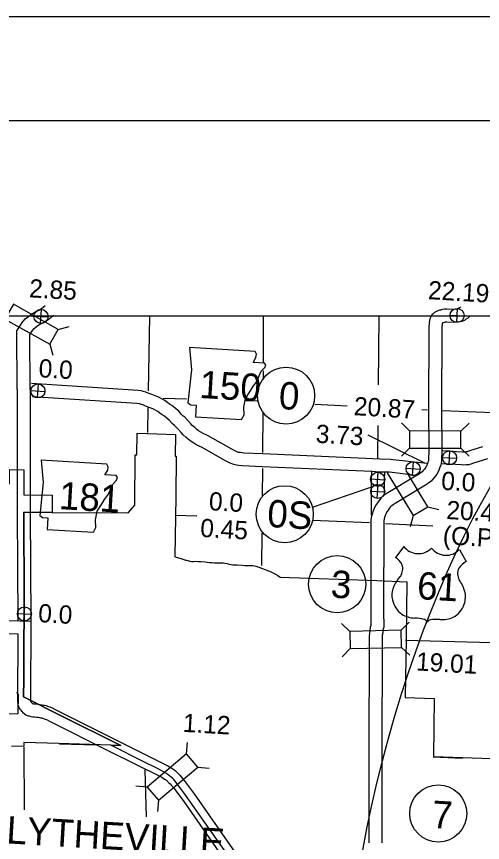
# Model space of a CAD drawing. Extents: x 1366406 to 1373462, y 376856 to 381998.
# Drawn here: x 1368068.6 to 1368242.9, y 380963.4 to 381272.9 of the extents above; entities that cross this region are included whole.
import ezdxf

# ---------------------------------------------------------------- set-up
doc = ezdxf.new("R2010")
doc.units = 0
for name, color, linetype in [('10', 7, 'Continuous'), ('15', 7, 'Continuous'), ('20', 7, 'Continuous'), ('21', 7, 'Continuous'), ('22', 7, 'Continuous'), ('25', 7, 'Continuous'), ('26', 7, 'Continuous'), ('27', 7, 'Continuous'), ('4', 7, 'Continuous'), ('5', 7, 'Continuous'), ('58', 7, 'Continuous'), ('6', 7, 'Continuous'), ('Default', 7, 'Continuous'), ('R_Border', 7, 'Continuous'), ('R_No Plot', 7, 'Continuous')]:
    doc.layers.add(name, color=color, linetype=linetype)

msp = doc.modelspace()

# ---------------------------------------------------------------- linework, layer by layer
at = {"layer": '10'}
for points in [[(1368068.72, 381155.1), (1368070.02, 381157.19), (1368070.68, 381158.2), (1368071.82, 381159.55), (1368073.08, 381160.5), (1368074.35, 381161.46), (1368075.71, 381162.23), (1368076.88, 381162.88), (1368077.85, 381163.48), (1368078.64, 381164.12), (1368079.34, 381164.66)], [(1368073.59, 381153.78), (1368074.1, 381154.54), (1368074.59, 381155.3), (1368075.17, 381155.98), (1368076.09, 381156.72), (1368076.97, 381157.38), (1368078.12, 381158.03), (1368079.39, 381158.71), (1368080.72, 381159.55), (1368081.7, 381160.34), (1368082.49, 381160.96)], [(1368068.79, 381133.08), (1368068.73, 381155.1)], [(1368073.65, 381133.1), (1368073.59, 381153.78)], [(1368073.65, 381133.1), (1368073.59, 381153.63)], [(1368204.48, 381107), (1368201.84, 381107.22), (1368160.75, 381109.02), (1368153.57, 381109.33), (1368152.33, 381109.53), (1368151.69, 381109.59), (1368151.3, 381109.68), (1368150.53, 381110), (1368149.08, 381110.73), (1368139.98, 381115.87), (1368138.36, 381116.6), (1368137.55, 381117.14), (1368136.7, 381117.69), (1368135.97, 381118.23), (1368135.23, 381118.87), (1368134.32, 381119.64), (1368133.8, 381120.26), (1368132.65, 381121.52), (1368131.53, 381122.72), (1368130.82, 381123.3), (1368130.34, 381123.73), (1368129.3, 381125), (1368127.94, 381126.15), (1368126.71, 381127.13), (1368125.86, 381127.65), (1368125.21, 381128.17), (1368124.08, 381129), (1368121.63, 381130.27), (1368118.59, 381131.48), (1368117.51, 381131.89), (1368116.89, 381132.13), (1368115.99, 381132.44), (1368115.29, 381132.58), (1368114.13, 381132.74), (1368074.18, 381135.33)], [(1368068.79, 381133.09), (1368068.84, 381087.06), (1368069.03, 381046.57)], [(1368073.65, 381133.09), (1368073.7, 381087.08), (1368073.9, 381046.43)], [(1368204.26, 381102.14), (1368201.53, 381102.37), (1368160.54, 381104.16), (1368153.07, 381104.49), (1368151.72, 381104.71), (1368150.94, 381104.78), (1368149.85, 381105.02), (1368148.51, 381105.57), (1368146.79, 381106.44), (1368137.77, 381111.53), (1368135.99, 381112.34), (1368134.89, 381113.08), (1368133.95, 381113.68), (1368132.94, 381114.42), (1368132.06, 381115.18), (1368130.87, 381116.19), (1368130.14, 381117.06), (1368129.08, 381118.23), (1368128.2, 381119.16), (1368127.65, 381119.61), (1368126.82, 381120.36), (1368125.82, 381121.58), (1368124.86, 381122.4), (1368123.93, 381123.13), (1368123.06, 381123.66), (1368122.25, 381124.32), (1368121.5, 381124.86), (1368119.6, 381125.85), (1368116.83, 381126.95), (1368115.79, 381127.34), (1368115.23, 381127.56), (1368114.72, 381127.74), (1368114.48, 381127.78), (1368113.64, 381127.9), (1368074.54, 381130.44)], [(1368242.98, 381111.68), (1368238.02, 381110.11), (1368237.17, 381109.83), (1368236.98, 381109.79), (1368236.85, 381109.77), (1368236.27, 381109.72), (1368235.89, 381109.66), (1368235.42, 381109.71), (1368233.21, 381109.83), (1368230.68, 381110.03), (1368228.08, 381110.14)], [(1368021.88, 381107.98), (1368036.86, 381077.38), (1368053.85, 381042.05), (1368069.03, 381041.63)], [(1368026.24, 381110.12), (1368041.23, 381079.5), (1368056.94, 381046.83), (1368073.92, 381046.36)], [(1368244.84, 381107.17), (1368239.52, 381105.49), (1368238.53, 381105.16), (1368237.78, 381104.97), (1368237.29, 381104.93), (1368236.84, 381104.89), (1368235.98, 381104.77), (1368235.06, 381104.86), (1368232.88, 381104.98), (1368230.39, 381105.18), (1368227.8, 381105.28)], [(1368222.06, 381105.39), (1368208.4, 381106.97), (1368204.48, 381107)], [(1368201.42, 381102.25), (1368201.41, 381102.16), (1368201.38, 381101.61), (1368201.23, 381100.63), (1368201.33, 381086.11)], [(1368217.93, 381100.97), (1368208.1, 381102.12), (1368204.26, 381102.14)], [(1368206.27, 381102), (1368206.22, 381101.12), (1368206.1, 381100.29), (1368206.14, 381093.75)], [(1368073.92, 381046.36), (1368073.75, 381017.15), (1368073.78, 381016.51), (1368073.81, 381016.29), (1368073.86, 381016.18), (1368073.94, 381016.09), (1368074.14, 381015.89), (1368074.42, 381015.6), (1368074.45, 381015.56), (1368074.53, 381015.54), (1368074.68, 381015.48), (1368074.86, 381015.44), (1368075.18, 381015.39), (1368075.8, 381015.34), (1368076.58, 381015.24), (1368077.38, 381015.17), (1368077.9, 381015.07), (1368078.19, 381015.04), (1368078.71, 381014.9), (1368079.02, 381014.84), (1368079.61, 381014.7), (1368080.12, 381014.54), (1368080.56, 381014.39), (1368081.02, 381014.23), (1368081.5, 381014.03), (1368082.22, 381013.77), (1368082.48, 381013.55), (1368083.22, 381013.13), (1368105.46, 381002.03), (1368125.19, 380992.14), (1368126.41, 380991.43), (1368127.09, 380991.05), (1368127.59, 380990.64), (1368127.91, 380990.39), (1368128.43, 380989.93), (1368128.76, 380989.53), (1368129.03, 380989.23), (1368129.64, 380988.61), (1368130.13, 380988.02), (1368131.28, 380986.69), (1368135.09, 380981.67), (1368155.97, 380951.57)], [(1368069.03, 381041.63), (1368068.89, 381017.03), (1368068.94, 381016.05), (1368068.99, 381015.7), (1368069.04, 381015.09), (1368069.26, 381014.57), (1368069.47, 381014.07), (1368069.8, 381013.43), (1368070.18, 381012.99), (1368070.48, 381012.68), (1368070.68, 381012.48), (1368070.69, 381012.47), (1368070.86, 381012.24), (1368071.3, 381011.85), (1368071.42, 381011.75), (1368071.58, 381011.63), (1368071.99, 381011.3), (1368072.57, 381011.07), (1368072.91, 381010.95), (1368073.24, 381010.83), (1368073.9, 381010.66), (1368074.64, 381010.56), (1368075.31, 381010.51), (1368076.05, 381010.41), (1368076.71, 381010.35), (1368077.19, 381010.26), (1368077.28, 381010.25), (1368077.66, 381010.14), (1368078.03, 381010.08), (1368078.31, 381010.01), (1368078.6, 381009.92), (1368078.96, 381009.8), (1368079.3, 381009.68), (1368079.81, 381009.47), (1368080.94, 381008.83), (1368103.29, 380997.68), (1368122.88, 380987.87), (1368123.99, 380987.22), (1368124.33, 380987.03), (1368124.57, 380986.83), (1368124.81, 380986.64), (1368124.93, 380986.54), (1368125.1, 380986.33), (1368125.49, 380985.9), (1368126.03, 380985.36), (1368126.42, 380984.88), (1368127.5, 380983.63), (1368131.16, 380978.81), (1368151.08, 380950.1)]]:
    msp.add_lwpolyline(points, dxfattribs=at)
at = {"layer": '15'}
for points in [[(1368234.67, 381164), (1368233.8, 381163.35), (1368233.62, 381163.22), (1368233.61, 381163.22), (1368233.45, 381163.2), (1368232.66, 381163.19), (1368231.91, 381163.13), (1368229.59, 381163.22), (1368228.66, 381163.18), (1368227.94, 381163.09), (1368227.42, 381162.94), (1368227.33, 381162.91), (1368226.82, 381162.81), (1368226.17, 381162.57), (1368225.48, 381162.25), (1368224.99, 381161.96), (1368224.5, 381161.54), (1368224.03, 381161.09), (1368223.55, 381160.34), (1368223.21, 381159.66), (1368222.94, 381158.27), (1368222.9, 381156.39), (1368222.77, 381125.53), (1368222.85, 381110.61), (1368222.85, 381109.14), (1368222.79, 381108.09), (1368222.79, 381107.87)], [(1368238.15, 381160.6), (1368237.36, 381159.76), (1368236.75, 381159.49), (1368236.62, 381159.39), (1368236.44, 381159.27), (1368236.15, 381159.03), (1368235.6, 381158.79), (1368235.17, 381158.6), (1368234.58, 381158.43), (1368233.71, 381158.35), (1368232.88, 381158.33), (1368232.01, 381158.27), (1368229.6, 381158.36), (1368229.08, 381158.34), (1368228.95, 381158.32), (1368228.65, 381158.23), (1368228.35, 381158.16), (1368228.15, 381158.12), (1368228.05, 381158.08), (1368227.84, 381157.99), (1368227.79, 381157.75), (1368227.76, 381156.32), (1368227.63, 381125.53), (1368227.71, 381110.62), (1368227.71, 381109), (1368227.65, 381107.9), (1368227.64, 381107.76)], [(1368222.79, 381108), (1368222.7, 381106.72), (1368222.67, 381106.42), (1368222.5, 381105.9), (1368222.33, 381105.46), (1368221.96, 381104.45)], [(1368227.64, 381107.64), (1368227.54, 381106.35), (1368227.47, 381105.4), (1368227.3, 381104.94), (1368227.08, 381104.26), (1368226.87, 381103.73), (1368226.45, 381102.58)], [(1368222.12, 381104.81), (1368221.67, 381104), (1368221.24, 381103.34), (1368220.76, 381102.81), (1368220.36, 381102.35), (1368219.87, 381101.97), (1368218.96, 381101.32), (1368217.22, 381100.31), (1368207.56, 381094.49), (1368206.7, 381093.87), (1368206.15, 381093.5), (1368205.54, 381093.02), (1368205.01, 381092.54), (1368204.59, 381092.05), (1368204.12, 381091.39), (1368203.59, 381090.68), (1368202.95, 381089.7), (1368202.37, 381088.54), (1368201.98, 381087.64), (1368201.63, 381086.49), (1368201.39, 381085.64), (1368201.2, 381084.47)], [(1368226.45, 381102.58), (1368225.83, 381101.48), (1368225.11, 381100.38), (1368224.39, 381099.58), (1368223.7, 381098.79), (1368222.77, 381098.07), (1368221.6, 381097.24), (1368219.7, 381096.13), (1368210.24, 381090.43), (1368209.48, 381089.89), (1368209.01, 381089.57), (1368208.69, 381089.31), (1368208.5, 381089.14), (1368208.42, 381089.04), (1368208.05, 381088.53), (1368207.58, 381087.89), (1368207.17, 381087.27), (1368206.77, 381086.47), (1368206.54, 381085.96), (1368206.29, 381085.13), (1368206.14, 381084.6), (1368206.03, 381083.89)], [(1368201.2, 381084.47), (1368201.09, 381048.75), (1368201.1, 381045.59), (1368201.1, 381044.77), (1368200.91, 381044.07), (1368200.77, 381042.72), (1368200.6, 381041.75), (1368200.53, 381040.95), (1368200.52, 381040.26), (1368200.53, 381039.5), (1368200.43, 380996.28), (1368200.37, 380963.27)], [(1368206.06, 381084.27), (1368205.95, 381048.75), (1368205.96, 381045.6), (1368205.97, 381044.11), (1368205.7, 381043.16), (1368205.58, 381042.04), (1368205.42, 381041.13), (1368205.39, 381040.7), (1368205.38, 381040.25), (1368205.39, 381039.55), (1368205.29, 380996.27), (1368205.23, 380963.26)]]:
    msp.add_lwpolyline(points, dxfattribs=at)
at = {"layer": '20'}
for p, q in [((1368084.15, 381155.65), (1368088.27, 381156.79)), ((1368081, 381150.06), (1368082.14, 381145.94)), ((1368215.65, 381117.62), (1368212.63, 381120.66)), ((1368234.89, 381117.56), (1368237.93, 381120.58)), ((1368215.63, 381111.21), (1368212.59, 381108.19)), ((1368234.87, 381111.15), (1368237.89, 381108.12)), ((1368207.27, 381101.94), (1368216.94, 381085.9)), ((1368222.43, 381089.2), (1368215.22, 381101.19)), ((1368216.94, 381085.9), (1368222.43, 381089.2)), ((1368222.43, 381089.2), (1368226.59, 381088.17)), ((1368216.94, 381085.9), (1368215.91, 381081.74)), ((1368193.28, 381042.54), (1368190.19, 381045.51)), ((1368212.52, 381042.93), (1368215.48, 381046.02)), ((1368193.41, 381036.13), (1368190.44, 381033.04)), ((1368212.65, 381036.52), (1368215.73, 381033.56)), ((1368132.21, 380996.6), (1368132.58, 381000.86)), ((1368136.35, 380991.69), (1368140.61, 380991.33)), ((1368117.5, 380984.19), (1368113.24, 380984.56)), ((1368121.63, 380979.29), (1368121.27, 380975.03))]:
    msp.add_line(p, q, dxfattribs=at)
for points in [[(1368084.15, 381155.65), (1368067.39, 381165.11), (1368064.24, 381159.53), (1368081, 381150.06)], [(1368234.89, 381117.56), (1368215.65, 381117.62), (1368215.63, 381111.21), (1368234.87, 381111.15)], [(1368212.52, 381042.93), (1368193.28, 381042.54), (1368193.41, 381036.13), (1368212.65, 381036.52)], [(1368121.63, 380979.29), (1368136.35, 380991.69), (1368132.21, 380996.6), (1368117.5, 380984.19)]]:
    msp.add_lwpolyline(points, close=True, dxfattribs=at)
at = {"layer": '21'}
for points in [[(1368133.23, 381148.83), (1368133.98, 381140.55), (1368132.7, 381128.13), (1368133.76, 381127.38), (1368135.81, 381127.26), (1368135.55, 381122.88), (1368152.79, 381121.87), (1368153.71, 381123.6), (1368153.61, 381126.49), (1368154.21, 381129.75), (1368155.87, 381132.26), (1368156.94, 381134.12), (1368158.43, 381136.09), (1368159.38, 381138.23), (1368160.17, 381139.97), (1368161.49, 381141.4), (1368161.82, 381142.34), (1368161.31, 381143.06), (1368157.07, 381143.31), (1368158.14, 381145.16), (1368158.35, 381146.39), (1368157.84, 381147.37)], [(1368077.76, 381106.64), (1368078.51, 381098.36), (1368077.23, 381085.94), (1368078.28, 381085.19), (1368080.34, 381085.07), (1368080.08, 381080.69), (1368097.32, 381079.68), (1368098.24, 381081.41), (1368098.14, 381084.3), (1368098.74, 381087.56), (1368100.4, 381090.07), (1368101.47, 381091.93), (1368102.96, 381093.9), (1368103.91, 381096.04), (1368104.7, 381097.78), (1368106.02, 381099.21), (1368106.35, 381100.15), (1368105.84, 381100.87), (1368101.6, 381101.12), (1368102.67, 381102.97), (1368102.88, 381104.2), (1368102.37, 381105.18)]]:
    msp.add_lwpolyline(points, close=True, dxfattribs=at)
at = {"layer": '22'}
for p, q in [((1368213.45, 381074.38), (1368210.4, 381070.22)), ((1368234.27, 381073.15), (1368236.81, 381068.66))]:
    msp.add_line(p, q, dxfattribs=at)
for centre, radius, start, end in [((1368218.92, 381078.46), 6.82, 216.7045, 316.2996), ((1368229.31, 381077.85), 6.82, 216.9593, 316.5544), ((1368206.37, 381064.15), 7.28, 27.4103, 56.6177), ((1368208.09, 381065.97), 4.99, 325.4399, 17.8402), ((1368240.1, 381062.16), 7.28, 116.6412, 145.8485), ((1368238.61, 381064.17), 4.99, 155.4187, 207.819), ((1368220.52, 381054.99), 11.65, 135.5859, 159.3208), ((1368224.97, 381054.72), 11.65, 13.9381, 37.673), ((1368216.74, 381056.16), 7.7, 157.5871, 194.0113), ((1368228.87, 381055.45), 7.7, 339.2476, 15.6718), ((1368217.99, 381056.11), 8.91, 191.7369, 233.7606), ((1368227.62, 381055.55), 8.91, 299.4982, 341.522), ((1368218.32, 381058.9), 11.44, 240.7065, 266.2073), ((1368216.68, 381026.56), 20.95, 77.8236, 87.5833), ((1368220.4, 381045.16), 2.01, 24.6637, 69.6158), ((1368223.94, 381044.95), 2.01, 103.6431, 148.5952), ((1368225.45, 381026.04), 20.95, 85.6756, 95.4353), ((1368227.62, 381058.36), 11.44, 267.0516, 292.5524)]:
    msp.add_arc(centre, radius, start, end, dxfattribs=at)
at = {"layer": '25'}
msp.add_line((1368200.01, 381116.15), (1368221.21, 381105.69), dxfattribs=at)
at = {"layer": '26'}
for p, q in [((1368077.56, 381157.88), (1368077.87, 381163.13)), ((1368233.27, 381158.23), (1368233.58, 381163.48)), ((1368075.09, 381160.66), (1368080.34, 381160.35)), ((1368230.8, 381161.01), (1368236.06, 381160.7)), ((1368076.42, 381129.96), (1368076.73, 381135.22)), ((1368073.95, 381132.74), (1368079.21, 381132.43)), ((1368227.98, 381107.67), (1368233.24, 381107.36)), ((1368230.46, 381104.89), (1368230.77, 381110.14)), ((1368216.8, 381100.84), (1368217.11, 381106.1)), ((1368203.55, 381096.85), (1368203.86, 381102.11)), ((1368214.33, 381103.62), (1368219.58, 381103.31)), ((1368201.08, 381099.64), (1368206.34, 381099.33)), ((1368201.1, 381095.11), (1368206.35, 381094.8)), ((1368203.57, 381092.33), (1368203.88, 381097.58)), ((1368071.34, 381046.44), (1368071.65, 381051.7)), ((1368068.87, 381049.23), (1368074.13, 381048.92))]:
    msp.add_line(p, q, dxfattribs=at)
for centre in [(1368077.72, 381160.51), (1368233.43, 381160.85), (1368076.58, 381132.59), (1368230.61, 381107.51), (1368216.96, 381103.47), (1368203.71, 381099.48), (1368203.72, 381094.95), (1368071.5, 381049.07)]:
    msp.add_circle(centre, 2.63, dxfattribs=at)
at = {"layer": '27'}
msp.add_line((1368179.34, 381089.08), (1368201.11, 381096.53), dxfattribs=at)
for centre in [(1368169.43, 381130.84), (1368168.91, 381086.42), (1368188.54, 381060.2), (1368226.39, 380974.31)]:
    msp.add_circle(centre, 10.69, dxfattribs=at)
at = {"layer": '4'}
for points in [[(1368214.1, 381039.24), (1368246.43, 381038.32), (1368284.69, 381037.31)], [(1368071.24, 380999.15), (1368071.43, 380975.68)]]:
    msp.add_lwpolyline(points, dxfattribs=at)
at = {"layer": '5'}
for points in [[(1368118.33, 381160.5), (1368117.77, 381132.66)], [(1368160.85, 381160.46), (1368160.83, 381143.08)], [(1368204.18, 381160.44), (1368203.87, 381134.84)], [(1368160.82, 381140.16), (1368160.82, 381136.94)], [(1368123.38, 381129.92), (1368132.11, 381129.65)], [(1368154.38, 381128.97), (1368158.58, 381128.84)], [(1368117.69, 381126.53), (1368117.62, 381116.98)], [(1368180.17, 381127.65), (1368192.24, 381126.96)], [(1368160.76, 381124.37), (1368160.62, 381109.55)], [(1368220.29, 381125.61), (1368222.32, 381125.53)], [(1368227.81, 381125.31), (1368246.97, 381124.52), (1368271.14, 381122.8)], [(1368203.74, 381119.65), (1368203.7, 381107.35)], [(1368160.56, 381103.58), (1368160.46, 381093.28)], [(1368127.95, 381086.1), (1368136, 381085.82)], [(1368179.37, 381084.17), (1368200.67, 381083.26)], [(1368206.64, 381082.99), (1368224.35, 381082.09)], [(1368160.32, 381079.38), (1368160.18, 381067.16)], [(1368084.68, 381000.43), (1368098.28, 381000.02)], [(1368224.5, 380995.47), (1368235.41, 380995.07)], [(1368116.61, 380990.67), (1368117.1, 380973.01)]]:
    msp.add_lwpolyline(points, dxfattribs=at)
at = {"layer": '6'}
for points in [[(1368081.89, 381087.1), (1368110.39, 381086.91), (1368112.88, 381089.75), (1368113.01, 381108.65), (1368113.63, 381108.63), (1368113.72, 381116.75), (1368117.57, 381116.62), (1368128, 381116.27), (1368127.93, 381108.13), (1368128.28, 381108.11), (1368128.17, 381093.04), (1368127.83, 381070.47)], [(1368050.05, 381087.37), (1368060.54, 381087.28), (1368060.59, 381097.88), (1368065.94, 381097.82), (1368065.98, 381103.16), (1368071.35, 381103.1), (1368071.33, 381100.43), (1368071.3, 381096.85), (1368071.28, 381094.3), (1368071.27, 381093.68), (1368081.94, 381093.61), (1368081.89, 381087.1)], [(1368071.26, 381085.4), (1368071.24, 381087.18)], [(1368071.24, 381087.18), (1368081.89, 381087.1)], [(1368081.89, 381087.1), (1368071.24, 381087.18)], [(1368071.24, 381087.18), (1368071.26, 381085.4)], [(1368071.28, 381082.72), (1368071.26, 381085.4)], [(1368071.26, 381085.4), (1368071.28, 381082.72)], [(1368071.3, 381080.02), (1368071.28, 381082.72)], [(1368071.28, 381082.72), (1368071.3, 381080.02)], [(1368071.34, 381075.93), (1368071.3, 381080.02)], [(1368071.3, 381080.02), (1368071.34, 381075.93)], [(1368071.35, 381074), (1368071.34, 381075.93)], [(1368071.34, 381075.93), (1368071.35, 381074)], [(1368071.35, 381071.98), (1368071.35, 381074)], [(1368071.35, 381074), (1368071.35, 381071.98)], [(1368071.39, 381069.18), (1368071.35, 381071.98)], [(1368071.35, 381071.98), (1368071.39, 381069.18)], [(1368127.83, 381070.47), (1368130.53, 381069.74), (1368130.83, 381069.61), (1368131.53, 381069.33), (1368131.78, 381069.25), (1368132.16, 381069.16), (1368132.65, 381069.07), (1368132.98, 381068.99), (1368133.31, 381068.85), (1368133.57, 381068.81), (1368134.13, 381068.75), (1368134.68, 381068.75), (1368135.3, 381068.77), (1368136.51, 381068.74), (1368137.53, 381068.69), (1368139.15, 381068.54), (1368140.68, 381068.35), (1368141.32, 381068.28), (1368141.78, 381068.27), (1368142.6, 381068.26), (1368143.37, 381068.18), (1368144.09, 381068.17), (1368144.65, 381068.2), (1368145.2, 381068.21), (1368145.84, 381068.17), (1368146.57, 381068.05), (1368147.36, 381067.94), (1368148.14, 381067.73), (1368148.8, 381067.59), (1368149.56, 381067.5), (1368151.11, 381067.42), (1368153.04, 381067.27), (1368153.99, 381067.26), (1368155.71, 381067.26), (1368156.93, 381067.23), (1368157.56, 381067.12), (1368158.09, 381066.91), (1368159.29, 381066.52), (1368160.2, 381066.17), (1368162.85, 381065.22), (1368163.84, 381064.81), (1368164.7, 381064.38), (1368165.49, 381063.93), (1368166.33, 381063.45), (1368167.27, 381062.84), (1368203.46, 381061.59), (1368214.61, 381061.12), (1368214.35, 381039.47), (1368213.98, 381017.77), (1368224.83, 381017.39), (1368224.62, 380995.67), (1368246.34, 380994.89)], [(1368071.4, 381063.93), (1368071.39, 381069.18)], [(1368071.39, 381069.18), (1368071.4, 381063.93)], [(1368071.4, 381062.78), (1368071.4, 381063.93)], [(1368071.4, 381063.93), (1368071.4, 381062.78)], [(1368071.43, 381059.6), (1368071.4, 381062.78)], [(1368071.4, 381062.78), (1368071.43, 381059.6)], [(1368071.45, 381054.93), (1368071.43, 381059.6)], [(1368071.43, 381059.6), (1368071.45, 381054.93)], [(1368071.47, 381053.69), (1368071.45, 381054.93)], [(1368071.45, 381054.93), (1368071.47, 381053.69)], [(1368071.43, 381048.91), (1368071.44, 381052.52)], [(1368071.44, 381052.52), (1368071.43, 381048.91)], [(1368071.44, 381052.52), (1368071.47, 381053.69)], [(1368071.47, 381053.69), (1368071.44, 381052.52)], [(1368071.42, 381047.21), (1368071.43, 381048.91)], [(1368071.43, 381048.91), (1368071.42, 381047.21)], [(1368071.38, 381044.14), (1368071.4, 381045.78)], [(1368071.4, 381045.78), (1368071.38, 381044.14)], [(1368071.4, 381045.78), (1368071.42, 381047.21)], [(1368071.42, 381047.21), (1368071.4, 381045.78)], [(1368071.34, 381042.54), (1368071.38, 381044.14)], [(1368071.38, 381044.14), (1368071.34, 381042.54)], [(1368071.34, 381040.17), (1368071.34, 381042.54)], [(1368071.34, 381042.54), (1368071.34, 381040.17)], [(1368071.31, 381037.14), (1368071.34, 381040.17)], [(1368071.34, 381040.17), (1368071.31, 381037.14)], [(1368071.3, 381033.67), (1368071.31, 381037.14)], [(1368071.31, 381037.14), (1368071.3, 381033.67)], [(1368071.31, 381030.39), (1368071.3, 381033.67)], [(1368071.3, 381033.67), (1368071.31, 381030.39)], [(1368071.31, 381026.1), (1368071.31, 381030.39)], [(1368071.31, 381030.39), (1368071.31, 381026.1)], [(1368071.26, 381022.63), (1368071.31, 381026.1)], [(1368071.31, 381026.1), (1368071.26, 381022.63)], [(1368071.23, 381019.96), (1368071.26, 381022.63)], [(1368071.26, 381022.63), (1368071.23, 381019.96)], [(1368060.53, 381011.56), (1368069.23, 381011.77), (1368069.28, 381018.87), (1368068.55, 381019.66)], [(1368071.23, 381017.97), (1368071.23, 381019.96)], [(1368071.23, 381019.96), (1368071.23, 381017.97)], [(1368084.49, 381011.26), (1368071.23, 381017.97)], [(1368071.23, 381017.97), (1368084.49, 381011.26)], [(1368107.61, 380999.8), (1368084.49, 381011.26)], [(1368084.49, 381011.26), (1368107.61, 380999.8)], [(1368071.28, 381000.94), (1368071.26, 380999.52), (1368066.72, 380999.4)], [(1368103.8, 380999.92), (1368084.39, 381000.53), (1368071.28, 381000.94)], [(1368147.18, 380959.38), (1368139.07, 380970.94), (1368135.12, 380976.38), (1368131.3, 380981.87), (1368128.69, 380985.37), (1368127.37, 380987.01), (1368126.92, 380987.52), (1368125.3, 380988.82), (1368124.64, 380989.31), (1368123.79, 380989.82), (1368123, 380990.25), (1368120.8, 380991.41), (1368116.24, 380993.71), (1368103.8, 380999.92)], [(1368103.8, 380999.92), (1368107.61, 380999.8)], [(1368107.61, 380999.8), (1368103.8, 380999.92)]]:
    msp.add_lwpolyline(points, dxfattribs=at)
at = {"layer": 'Default'}
msp.add_ellipse((1368265.23, 380986.62), major_axis=(44.98, 163.09), ratio=0.352669, dxfattribs=at)
at = {"layer": 'R_Border'}
msp.add_line((1367815.86, 381233.92), (1370977.66, 381233.92), dxfattribs=at)
at = {"layer": 'R_No Plot'}
msp.add_line((1367691.85, 381272.86), (1371025.18, 381272.86), dxfattribs=at)
msp.add_lwpolyline([(1367691.79, 381272.86), (1371025.18, 381272.86), (1371025.18, 379139.49), (1367691.79, 379139.49)], close=True, dxfattribs=at)
msp.add_lwpolyline([(1367869.99, 380474.3), (1367869.99, 381160.75), (1368650.02, 381160.75), (1368650.02, 380474.3), (1367869.99, 380474.3)], dxfattribs=at)

# ---------------------------------------------------------------- texts
at = {"layer": '21'}
for s, p in [('150', (1368136.82, 381129.99)), ('181', (1368084.24, 381088.35))]:
    msp.add_text(s, height=10.264, rotation=356.6294, dxfattribs=at).set_placement(p)
at = {"layer": '22'}
msp.add_text('61', height=10.264, rotation=356.6294, dxfattribs=at).set_placement((1368218.25, 381054.65))
at = {"layer": '25'}
for s, p in [('2.85', (1368073.14, 381167.7)), ('22.19', (1368222.42, 381167.01)), ('0.0', (1368076.69, 381137.75)), ('3.73', (1368180.4, 381113.23)), ('0.0', (1368227.35, 381095.6)), ('0.0', (1368140.42, 381087.95)), ('0.45', (1368137.17, 381077.95)), ('0.0', (1368076.54, 381046.02))]:
    msp.add_text(s, height=6.843, rotation=356.6294, dxfattribs=at).set_placement(p)
at = {"layer": '27'}
for s, height, p in [('0', 10.26, (1368166.51, 381125.87)), ('0S', 10.264, (1368162.18, 381081.67)), ('3', 10.26, (1368185.95, 381055.22)), ('7', 10.26, (1368223.81, 380968.93))]:
    msp.add_text(s, height=height, rotation=356.6294, dxfattribs=at).set_placement(p)
at = {"layer": '58'}
for s, p in [('20.87', (1368194.65, 381123.55)), ('20.41', (1368229.28, 381084.65)), ('(O.P.)', (1368227.96, 381075.19)), ('19.01', (1368217.92, 381027.93)), ('1.12', (1368130.64, 381004.91))]:
    msp.add_text(s, height=6.843, rotation=356.6294, dxfattribs=at).set_placement(p)
at = {"layer": '6'}
msp.add_text('BLYTHEVILLE', height=10.2643, rotation=356.6294, dxfattribs=at).set_placement((1368055.45, 380963.67))

doc.saveas('drawing.dxf')
